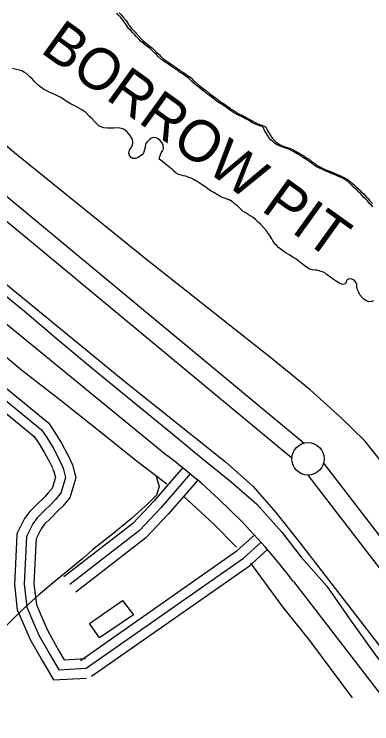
# Model space of a CAD drawing. Extents: x 3245246 to 3283090, y 806824 to 832173.
# Drawn here: x 3268870 to 3269420, y 814018 to 815112 of the extents above; entities that cross this region are included whole.
import ezdxf

# ---------------------------------------------------------------- set-up
doc = ezdxf.new("R2010")
doc.units = 0
for name, color, linetype in [('V-BLDG-OTLN', 7, 'Continuous'), ('V-BORW-IDEN', 7, 'Continuous'), ('V-BORW-LINE', 7, 'Continuous'), ('V-LEVE-TOET', 7, 'Continuous'), ('V-ROAD-CNTR', 7, 'Continuous'), ('V-SITE-VEGE', 7, 'Continuous'), ('V-SURV-LINE', 7, 'Continuous'), ('V-TOPO-SHOR', 7, 'Continuous')]:
    doc.layers.add(name, color=color, linetype=linetype)

msp = doc.modelspace()

# ---------------------------------------------------------------- linework, layer by layer
at = {"layer": 'V-BLDG-OTLN'}
msp.add_lwpolyline([(3269053, 814186), (3269001.1, 814150.8), (3268985.7, 814172.7), (3269036.3, 814208.4)], close=True, dxfattribs=at)
at = {"layer": 'V-BORW-LINE'}
for points in [[(3269031.1, 815114), (3269033.5, 815111.2), (3269037.3, 815107.3), (3269041.8, 815101.9), (3269045.7, 815096), (3269047.8, 815092.6), (3269049.9, 815089.8), (3269052.8, 815087), (3269055.8, 815084.2), (3269058.4, 815080.8), (3269061.4, 815077.8), (3269065.5, 815073.3), (3269067.9, 815070.8), (3269071.1, 815068), (3269075.5, 815064.7), (3269079.3, 815061.6), (3269082, 815059.9)], [(3269082, 815059.9), (3269084.6, 815057.4), (3269089.3, 815053), (3269092.6, 815049.9), (3269095, 815046.8), (3269099.9, 815042.3), (3269105.8, 815038.2), (3269110.8, 815035.2), (3269114, 815032.7), (3269118.7, 815029.6), (3269121.6, 815027.4), (3269125.1, 815025.2), (3269128, 815023), (3269133.3, 815019.7), (3269136.5, 815017.2), (3269141.8, 815013.6), (3269144.7, 815010.8), (3269148, 815007.8), (3269153.6, 815002.7), (3269158.5, 814998.9), (3269161.2, 814996.6), (3269165.3, 814993.9), (3269170.3, 814989.7), (3269175.8, 814985.5), (3269180.8, 814981.7), (3269184.3, 814978.9), (3269188.7, 814975.8), (3269191.9, 814974.2), (3269195.5, 814971.4), (3269200.1, 814968.4), (3269204.5, 814965.1), (3269208, 814962.9), (3269211, 814960.9), (3269214.5, 814958.7), (3269220.9, 814955.5), (3269224.4, 814953.8), (3269229.3, 814951.1), (3269232.2, 814949.7), (3269236, 814947.3), (3269240.4, 814945.1), (3269243.3, 814943.4), (3269247.4, 814941.8), (3269251.7, 814940.2), (3269254.9, 814939.4), (3269257.2, 814937.2), (3269258.8, 814933.2), (3269260.9, 814929.8), (3269263.3, 814925.9), (3269265.4, 814922.2), (3269268.4, 814918.8), (3269271.9, 814915.5), (3269274.2, 814913.5), (3269277.2, 814911.6), (3269281.2, 814909.4), (3269284.1, 814908.4), (3269287.9, 814907), (3269291.4, 814906), (3269296, 814904.4), (3269299.8, 814902.5), (3269302.7, 814900.8), (3269306.5, 814898.6), (3269309.1, 814897), (3269311.8, 814895.3), (3269314.7, 814894), (3269319.1, 814890.6), (3269323.5, 814888.2), (3269328.7, 814884), (3269332.5, 814881.5), (3269335.2, 814879.3), (3269338.7, 814877.1), (3269342.2, 814875.5), (3269349.1, 814872.2), (3269352.1, 814870.9), (3269356.1, 814869.2), (3269361.9, 814866.8), (3269368.3, 814864.1), (3269371.5, 814862.5), (3269375, 814861.1), (3269378.5, 814859.5), (3269383.4, 814856.8), (3269387.3, 814853.7), (3269393.1, 814848.4), (3269395.8, 814845.9), (3269399.3, 814842.8), (3269401.7, 814840.6), (3269404.1, 814837.8), (3269407, 814835.3), (3269411.7, 814830), (3269414.1, 814827.7), (3269416.5, 814824.9), (3269420.9, 814820.2)], [(3268973.7, 814964.6), (3268966.7, 814968.4), (3268960.6, 814971.7), (3268957.4, 814973), (3268951.9, 814976), (3268947.8, 814978.8), (3268941.6, 814983.2), (3268938.4, 814984.9), (3268931.1, 814988.7), (3268924.2, 814991.4), (3268919.8, 814993.6), (3268915.7, 814995.7), (3268911.1, 814998.8), (3268906.4, 815002.7), (3268904, 815004.9), (3268900.2, 815008.5), (3268897.5, 815011.6), (3268893.7, 815015.5), (3268891.3, 815017.8), (3268889, 815019.7), (3268885.2, 815021.9), (3268881.4, 815024.4), (3268877.9, 815025.7), (3268873, 815026.5), (3268867.2, 815028)], [(3269298.8, 814737.1), (3269293.6, 814740.4), (3269288.3, 814743.7), (3269282.5, 814747.8), (3269276.3, 814752.5), (3269273.6, 814755.3), (3269271.3, 814757.6), (3269267.7, 814762.4), (3269265.9, 814765.8), (3269262.9, 814770.8), (3269260.5, 814773.9), (3269257.8, 814777.9), (3269253.4, 814782.9), (3269248.4, 814788), (3269244.8, 814791.3), (3269241.3, 814794.7), (3269237.2, 814798.3), (3269232.8, 814801.3), (3269229.6, 814803.2), (3269225.2, 814806), (3269222, 814807.9), (3269218.7, 814810.7), (3269213.4, 814816.3), (3269208.7, 814819.6), (3269205.5, 814822.4), (3269200.2, 814825.7), (3269197.4, 814826.8), (3269193, 814828.4), (3269187.5, 814830.5), (3269183.4, 814833), (3269176.7, 814836.8), (3269173.5, 814838.8), (3269168.2, 814842.4), (3269164.4, 814845.1), (3269159.5, 814848.1), (3269157.1, 814850.1), (3269152.7, 814853.1), (3269146.6, 814856.7), (3269141.9, 814858.9), (3269138.5, 814860.2), (3269133.5, 814862.1), (3269130.3, 814862.9), (3269126.3, 814863.6), (3269122.2, 814864.9), (3269118.8, 814866.6), (3269114.9, 814870.2), (3269112.6, 814872.4), (3269109, 814875.5), (3269105.2, 814878.8), (3269100.8, 814882.2), (3269096.4, 814885.8), (3269092.9, 814888.6), (3269093.7, 814892.3), (3269094.7, 814895.2), (3269095.8, 814898.4), (3269097.7, 814901), (3269099.1, 814904.5), (3269098.9, 814910), (3269097.4, 814913.7), (3269094.4, 814917), (3269090.9, 814919.8), (3269088, 814921.4), (3269083.4, 814921.6), (3269079.7, 814920.4), (3269077.2, 814918.3), (3269074.4, 814915.3), (3269072.4, 814912.4), (3269071.1, 814908.4), (3269070.4, 814904.9), (3269068.5, 814898.2), (3269066.6, 814895.3), (3269064.1, 814893.5), (3269060.4, 814890.8), (3269056.1, 814889.3), (3269052.4, 814889.5), (3269049.5, 814891.1), (3269047.1, 814893.9), (3269046.1, 814897.9), (3269046.9, 814902.2), (3269049.1, 814905.2), (3269051, 814908.7), (3269052.4, 814912.4), (3269052.3, 814915.6), (3269051.6, 814918.7), (3269048.6, 814924.1), (3269046.2, 814927.5), (3269042.4, 814931.7), (3269038, 814934.7), (3269034.8, 814935.5), (3269029.6, 814936.5), (3269023.3, 814936.3), (3269016.4, 814936.2), (3269013, 814936.1), (3269007.5, 814936.5), (3269000.5, 814939.5), (3268997.6, 814942), (3268994, 814945.3), (3268989, 814950.9), (3268985.2, 814954.8), (3268979.6, 814960.1), (3268973.7, 814964.6)], [(3269422.3, 814670.3), (3269419.5, 814668.8), (3269415.2, 814668.7), (3269411.2, 814670), (3269407.9, 814672.5), (3269405.6, 814674.5), (3269401.7, 814679.3), (3269399.9, 814683), (3269397.8, 814686.9), (3269397.1, 814691.2), (3269396.7, 814695.2), (3269395.2, 814698.9), (3269392.8, 814702), (3269389, 814703.3), (3269385, 814704.1), (3269381.9, 814702.6), (3269380.5, 814699.4), (3269379.4, 814696.5), (3269375.4, 814695.5), (3269370.8, 814696.8), (3269366.4, 814699.3), (3269363.8, 814700.9), (3269360.9, 814702.9), (3269357.7, 814705.4), (3269355.3, 814707.3), (3269352.7, 814709), (3269350.3, 814710.9), (3269347.4, 814713.1), (3269343.9, 814714.7), (3269340.4, 814715.8), (3269335.5, 814717.1), (3269332.1, 814717.3), (3269328.6, 814717.8), (3269324, 814719.1), (3269318.7, 814722.4), (3269316.1, 814724), (3269312.3, 814727.7), (3269309.4, 814729.6), (3269305.5, 814732.9), (3269303.2, 814734.9), (3269298.8, 814737.1)]]:
    msp.add_lwpolyline(points, dxfattribs=at)
at = {"layer": 'V-LEVE-TOET'}
for points in [[(3267596.8, 815732.4), (3267840.3, 815535.2), (3267857.8, 815517.9), (3267863.6, 815508), (3267903, 815476.5), (3268218.9, 815217.6), (3268501.1, 814987), (3268787.8, 814752.2), (3269039.7, 814546), (3269194.6, 814422), (3269237.4, 814383.9), (3269272.2, 814344.1), (3269309.8, 814296.6), (3269553.2, 813980.9)], [(3269803.4, 813944.4), (3269654.7, 814141.9), (3269530, 814301.9), (3269409.2, 814454.2), (3269372.3, 814490.2), (3269325.2, 814533), (3269264.6, 814582.1), (3269070.9, 814735.1), (3268869.8, 814898.2), (3268651.4, 815084.2), (3268487.4, 815217.2), (3268295, 815374.6), (3268199.2, 815452.4), (3268175.9, 815479.2), (3268121.2, 815528.4)]]:
    msp.add_lwpolyline(points, dxfattribs=at)
at = {"layer": 'V-ROAD-CNTR'}
for points in [[(3266589.9, 816525.9), (3267314.9, 815916.9), (3268047.9, 815297.6), (3268901.3, 814598.7), (3269105.4, 814431.3)], [(3268519.8, 814793.4), (3268530.8, 814789.1), (3268556.3, 814781.3), (3268589.6, 814755.4), (3268923, 814481.4), (3268932.3, 814467.3), (3268942.3, 814450.8), (3268951.2, 814434.3), (3268952.1, 814432.5)], [(3268493.6, 814769.9), (3268502.6, 814767.9), (3268520.9, 814760.7), (3268542.3, 814754.2), (3268570.8, 814731.9), (3268900.4, 814461.2), (3268906.9, 814451.3), (3268916.3, 814435.9), (3268924.4, 814420.8), (3268928.3, 814412.5)], [(3268580.2, 814743.7), (3268911.7, 814471.3), (3268919.6, 814459.3), (3268929.3, 814443.3), (3268937.8, 814427.6), (3268945, 814412.2), (3268948.7, 814397.6), (3268941.6, 814373.7), (3268932.6, 814363.3), (3268927.3, 814357.7), (3268914.7, 814345.4), (3268905, 814335.8), (3268898.2, 814326.6), (3268888.6, 814307.1), (3268884.8, 814233.4), (3268889.1, 814198), (3268897.6, 814177.6), (3268907.7, 814154.9), (3268925.6, 814123.3), (3268938.4, 814101.5), (3268980.2, 814103.7)], [(3268952.1, 814432.5), (3268959.2, 814417.2), (3268964.3, 814397.3), (3268955, 814366.3), (3268943.7, 814353.3), (3268938, 814347.2), (3268925.2, 814334.7), (3268916.4, 814325.9), (3268911, 814318.7), (3268903.4, 814303.2), (3268903, 814295.3)], [(3268928.7, 814411.6), (3268930.8, 814407.1), (3268933.2, 814398), (3268928.1, 814381.1), (3268921.4, 814373.4), (3268916.6, 814368.2), (3268904.2, 814356.1), (3268893.7, 814345.6), (3268885.3, 814334.4), (3268873.7, 814310.9), (3268873.1, 814297.8)], [(3269129.2, 814413.1), (3269084.3, 814361.3), (3269052.1, 814327.1), (3268946.1, 814244.8)], [(3269140.5, 814403.3), (3269095.5, 814351.3), (3269062.2, 814316), (3268955.3, 814232.9)], [(3269151.9, 814393.4), (3269106.6, 814341.2), (3269072.3, 814304.8), (3268964.5, 814221.1)], [(3268971.6, 814116), (3269212.9, 814285.3), (3269239.3, 814309.1)], [(3268873.1, 814297.8), (3268869.8, 814232.9), (3268874.4, 814194.1), (3268883.8, 814171.6), (3268894.2, 814148.2), (3268912.6, 814115.8), (3268930.1, 814086.1), (3268980.9, 814088.7)], [(3268903, 814295.3), (3268899.9, 814234), (3268903.7, 814201.9), (3268911.4, 814183.5), (3268921.1, 814161.6), (3268938.5, 814130.8), (3268946.7, 814117), (3268979.4, 814118.7)], [(3268980.2, 814103.7), (3269222.3, 814273.5), (3269249.4, 814298)], [(3268988.8, 814091.4), (3269231.6, 814261.8), (3269259.4, 814286.9)], [(3269299.2, 814237.7), (3269774.1, 813621.1), (3270136.2, 813151.8)]]:
    msp.add_lwpolyline(points, dxfattribs=at)
msp.add_arc((3268481.7, 813613.5), 1028.5, 37.3643, 52.6688, dxfattribs=at)
at = {"layer": 'V-SITE-VEGE'}
for p, q in [((3269029.6, 815110.7), (3269027.3, 815113.6)), ((3269033.5, 815106.8), (3269029.6, 815110.7)), ((3269037.9, 815101.5), (3269033.5, 815106.8)), ((3269041.8, 815095.6), (3269037.9, 815101.5)), ((3269043.9, 815092.2), (3269041.8, 815095.6)), ((3269046, 815089.4), (3269043.9, 815092.2)), ((3269048.9, 815086.6), (3269046, 815089.4)), ((3269051.9, 815083.8), (3269048.9, 815086.6)), ((3269054.6, 815080.4), (3269051.9, 815083.8)), ((3269057.5, 815077.3), (3269054.6, 815080.4)), ((3269061.7, 815072.9), (3269057.5, 815077.3)), ((3269064, 815070.3), (3269061.7, 815072.9)), ((3269067.3, 815067.5), (3269064, 815070.3)), ((3269071.7, 815064.2), (3269067.3, 815067.5)), ((3269075.5, 815061.2), (3269071.7, 815064.2)), ((3269078.1, 815059.5), (3269075.5, 815061.2)), ((3269080.7, 815057), (3269078.1, 815059.5)), ((3269085.5, 815052.5), (3269080.7, 815057)), ((3269088.7, 815049.5), (3269085.5, 815052.5)), ((3269091.1, 815046.4), (3269088.7, 815049.5)), ((3269096.1, 815041.9), (3269091.1, 815046.4)), ((3269101.9, 815037.8), (3269096.1, 815041.9)), ((3269106.9, 815034.7), (3269101.9, 815037.8)), ((3269110.1, 815032.2), (3269106.9, 815034.7)), ((3269114.8, 815029.2), (3269110.1, 815032.2)), ((3269117.7, 815027), (3269114.8, 815029.2)), ((3269121.2, 815024.8), (3269117.7, 815027)), ((3269124.2, 815022.6), (3269121.2, 815024.8)), ((3269129.4, 815019.3), (3269124.2, 815022.6)), ((3269132.6, 815016.8), (3269129.4, 815019.3)), ((3269137.9, 815013.2), (3269132.6, 815016.8)), ((3269140.9, 815010.4), (3269137.9, 815013.2)), ((3269144.1, 815007.3), (3269140.9, 815010.4)), ((3269149.7, 815002.3), (3269144.1, 815007.3)), ((3269154.7, 814998.4), (3269149.7, 815002.3)), ((3269157.3, 814996.2), (3269154.7, 814998.4)), ((3269161.4, 814993.4), (3269157.3, 814996.2)), ((3269166.4, 814989.3), (3269161.4, 814993.4)), ((3269172, 814985.1), (3269166.4, 814989.3)), ((3269177, 814981.2), (3269172, 814985.1)), ((3269180.5, 814978.4), (3269177, 814981.2)), ((3269184.9, 814975.4), (3269180.5, 814978.4)), ((3269188.1, 814973.8), (3269184.9, 814975.4)), ((3269191.6, 814971), (3269188.1, 814973.8)), ((3269196.3, 814968), (3269191.6, 814971)), ((3269200.7, 814964.6), (3269196.3, 814968)), ((3269204.2, 814962.4), (3269200.7, 814964.6)), ((3269207.1, 814960.5), (3269204.2, 814962.4)), ((3269210.6, 814958.3), (3269207.1, 814960.5)), ((3269217, 814955), (3269210.6, 814958.3)), ((3269220.5, 814953.4), (3269217, 814955)), ((3269225.4, 814950.7), (3269220.5, 814953.4)), ((3269228.4, 814949.3), (3269225.4, 814950.7)), ((3269232.1, 814946.8), (3269228.4, 814949.3)), ((3269236.5, 814944.6), (3269232.1, 814946.8)), ((3269239.4, 814943), (3269236.5, 814944.6)), ((3269243.5, 814941.4), (3269239.4, 814943)), ((3269247.8, 814939.8), (3269243.5, 814941.4)), ((3269251, 814939), (3269247.8, 814939.8)), ((3269253.4, 814936.8), (3269251, 814939)), ((3269254.9, 814932.8), (3269253.4, 814936.8)), ((3269257, 814929.4), (3269254.9, 814932.8)), ((3269259.4, 814925.5), (3269257, 814929.4)), ((3269261.5, 814921.8), (3269259.4, 814925.5)), ((3269264.5, 814918.4), (3269261.5, 814921.8)), ((3269268, 814915.1), (3269264.5, 814918.4)), ((3269270.4, 814913.1), (3269268, 814915.1)), ((3269273.3, 814911.2), (3269270.4, 814913.1)), ((3269277.4, 814909), (3269273.3, 814911.2)), ((3269280.3, 814907.9), (3269277.4, 814909)), ((3269284.1, 814906.6), (3269280.3, 814907.9)), ((3269287.5, 814905.5), (3269284.1, 814906.6)), ((3269292.2, 814903.9), (3269287.5, 814905.5)), ((3269295.9, 814902), (3269292.2, 814903.9)), ((3269298.9, 814900.4), (3269295.9, 814902)), ((3269302.7, 814898.2), (3269298.9, 814900.4)), ((3269305.3, 814896.5), (3269302.7, 814898.2)), ((3269307.9, 814894.9), (3269305.3, 814896.5)), ((3269310.8, 814893.5), (3269307.9, 814894.9)), ((3269315.2, 814890.2), (3269310.8, 814893.5)), ((3269319.6, 814887.7), (3269315.2, 814890.2)), ((3269324.9, 814883.6), (3269319.6, 814887.7)), ((3269328.7, 814881.1), (3269324.9, 814883.6)), ((3269331.3, 814878.9), (3269328.7, 814881.1)), ((3269334.8, 814876.7), (3269331.3, 814878.9)), ((3269338.3, 814875), (3269334.8, 814876.7)), ((3269345.3, 814871.8), (3269338.3, 814875)), ((3269348.2, 814870.4), (3269345.3, 814871.8)), ((3269352.3, 814868.8), (3269348.2, 814870.4)), ((3269358.1, 814866.4), (3269352.3, 814868.8)), ((3269364.4, 814863.7), (3269358.1, 814866.4)), ((3269367.7, 814862.1), (3269364.4, 814863.7)), ((3269371.1, 814860.7), (3269367.7, 814862.1)), ((3269374.6, 814859.1), (3269371.1, 814860.7)), ((3269379.6, 814856.3), (3269374.6, 814859.1)), ((3269383.4, 814853.3), (3269379.6, 814856.3)), ((3269389.3, 814848), (3269383.4, 814853.3)), ((3269391.9, 814845.5), (3269389.3, 814848)), ((3269395.5, 814842.4), (3269391.9, 814845.5)), ((3269397.8, 814840.2), (3269395.5, 814842.4)), ((3269400.2, 814837.4), (3269397.8, 814840.2)), ((3269403.1, 814834.9), (3269400.2, 814837.4)), ((3269407.9, 814829.5), (3269403.1, 814834.9)), ((3269410.2, 814827.3), (3269407.9, 814829.5)), ((3269412.6, 814824.5), (3269410.2, 814827.3)), ((3269417, 814819.7), (3269412.6, 814824.5)), ((3269419.4, 814817.5), (3269417, 814819.7)), ((3269421.7, 814815), (3269419.4, 814817.5))]:
    msp.add_line(p, q, dxfattribs=at)
at = {"layer": 'V-SURV-LINE'}
for points in [[(3267544.3, 815922.9), (3269316, 814450.9)], [(3269296.8, 814427.8), (3267525.2, 815899.8)], [(3269345.8, 814419.9), (3270382.2, 813071.1)], [(3270358.4, 813052.8), (3269322, 814401.6)]]:
    msp.add_lwpolyline(points, dxfattribs=at)
msp.add_circle((3269321.7, 814426.6), 25, dxfattribs=at)
at = {"layer": 'V-TOPO-SHOR'}
for points in [[(3269104.3, 814387.3), (3269057.5, 814423.4), (3269005.1, 814465.4), (3268942.3, 814515.2), (3268881, 814563.1), (3268825.3, 814609.5), (3268766.2, 814657.4), (3268712.8, 814700.3), (3268652, 814750.3), (3268597.7, 814795.8), (3268525.3, 814851.7)], [(3268834.9, 814695.4), (3268885.4, 814654.1), (3268937.5, 814610), (3268987.2, 814568.2), (3269043.4, 814521.9), (3269110.5, 814467.4), (3269158.5, 814427.4), (3269203.7, 814391), (3269242.9, 814356.7), (3269281.3, 814313.7), (3269311.1, 814275), (3269350.7, 814230.3), (3269385.5, 814179.9), (3269427.3, 814122.1), (3269474.4, 814063.1), (3269518.3, 814006.6)], [(3269088.3, 814399.6), (3269092.8, 814383.9), (3269088.7, 814370.8), (3269076.2, 814358.5), (3269050.2, 814334.4), (3269023.3, 814312.7), (3268990.1, 814286.3), (3268975.3, 814273.1), (3268935.6, 814240.4), (3268907.6, 814216.8), (3268886, 814197.3), (3268864.1, 814175.8), (3268848.9, 814161.7), (3268837.1, 814151.9), (3268802.4, 814127.8), (3268764.9, 814101.8), (3268723.2, 814072.9), (3268666.8, 814034.1), (3268615.1, 813998.3)], [(3269211.6, 814290.6), (3269176.2, 814326.4), (3269131, 814368.1)], [(3269390.4, 814058.4), (3269324.7, 814146.8), (3269283, 814198.4), (3269233.7, 814265.6)]]:
    msp.add_lwpolyline(points, dxfattribs=at)

# ---------------------------------------------------------------- texts
at = {"layer": 'V-BORW-IDEN'}
msp.add_text('BORROW PIT', height=64, rotation=324.3247, dxfattribs=at).set_placement((3268908.1, 815054.2))

doc.saveas('drawing.dxf')
